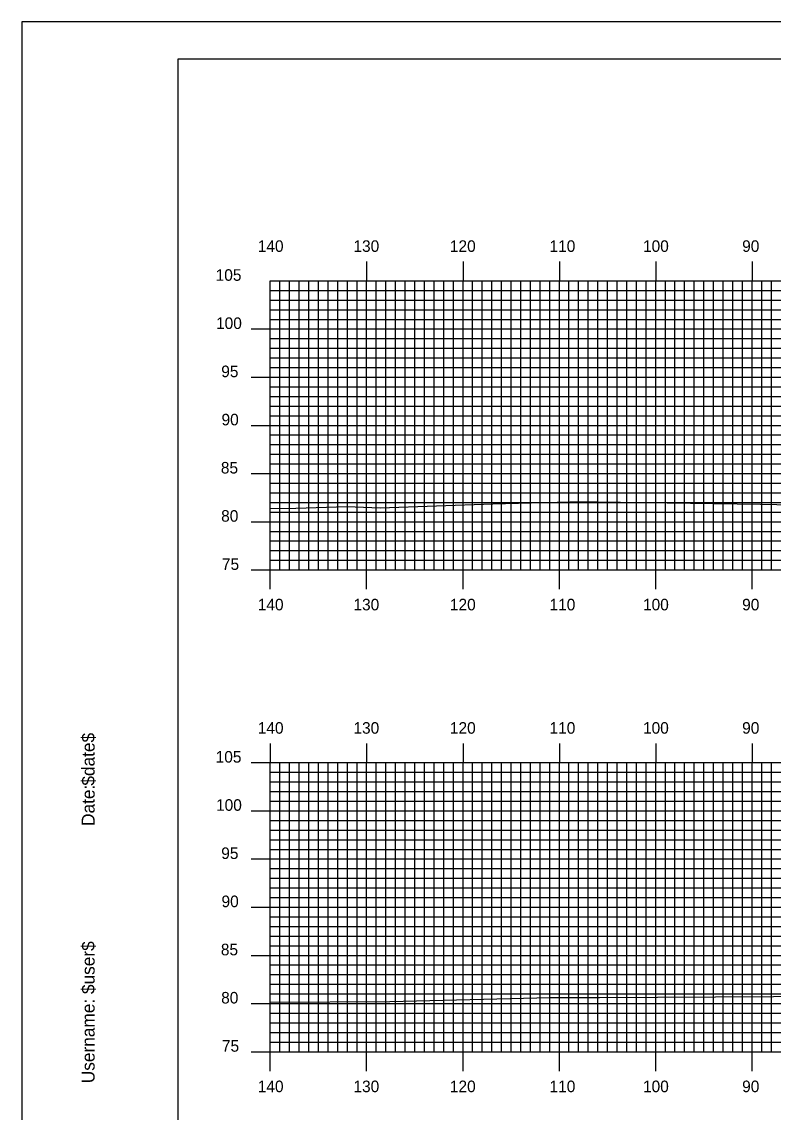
# Model space of a CAD drawing. Extents: x 1757462 to 1757806, y 442591 to 442811.
# Drawn here: x 1757462.3 to 1757540.3, y 442697.4 to 442810.5 of the extents above; entities that cross this region are included whole.
import ezdxf

# ---------------------------------------------------------------- set-up
doc = ezdxf.new("R2010")
doc.units = 0
for name, color, linetype in [('BORDER', 7, 'Continuous'), ('H_V ANNOTATION', 7, 'Continuous'), ('MAJOR', 7, 'Continuous'), ('MINOR', 7, 'Continuous'), ('PLOT BOUNDARY', 7, 'Continuous'), ('S_Roadway_Centerline', 7, 'Continuous')]:
    doc.layers.add(name, color=color, linetype=linetype)

msp = doc.modelspace()

# ---------------------------------------------------------------- linework, layer by layer
at = {"layer": 'BORDER'}
msp.add_lwpolyline([(1757478.51, 442596.67), (1757798.51, 442596.67), (1757798.51, 442806.67), (1757478.51, 442806.67)], close=True, dxfattribs=at)
at = {"layer": 'MAJOR'}
for p, q in [((1757498.11, 442785.67), (1757498.11, 442783.67)), ((1757508.11, 442785.67), (1757508.11, 442783.67)), ((1757518.11, 442785.67), (1757518.11, 442783.67)), ((1757528.11, 442785.67), (1757528.11, 442783.67)), ((1757538.11, 442785.67), (1757538.11, 442783.67)), ((1757488.11, 442783.67), (1757768.11, 442783.67)), ((1757488.11, 442753.67), (1757488.11, 442783.67)), ((1757488.11, 442753.67), (1757488.11, 442783.67)), ((1757488.11, 442783.67), (1757768.11, 442783.67)), ((1757498.11, 442753.67), (1757498.11, 442783.67)), ((1757508.11, 442753.67), (1757508.11, 442783.67)), ((1757518.11, 442753.67), (1757518.11, 442783.67)), ((1757528.11, 442753.67), (1757528.11, 442783.67)), ((1757538.11, 442753.67), (1757538.11, 442783.67)), ((1757486.11, 442778.67), (1757488.11, 442778.67)), ((1757488.11, 442778.67), (1757768.11, 442778.67)), ((1757486.11, 442773.67), (1757488.11, 442773.67)), ((1757488.11, 442773.67), (1757768.11, 442773.67)), ((1757486.11, 442768.67), (1757488.11, 442768.67)), ((1757488.11, 442768.67), (1757768.11, 442768.67)), ((1757486.11, 442763.67), (1757488.11, 442763.67)), ((1757488.11, 442763.67), (1757768.11, 442763.67)), ((1757486.11, 442758.67), (1757488.11, 442758.67)), ((1757488.11, 442758.67), (1757768.11, 442758.67)), ((1757486.11, 442753.67), (1757488.11, 442753.67)), ((1757488.11, 442753.67), (1757768.11, 442753.67)), ((1757488.11, 442753.67), (1757768.11, 442753.67)), ((1757488.11, 442751.66), (1757488.11, 442753.67)), ((1757498.11, 442751.66), (1757498.11, 442753.67)), ((1757508.11, 442751.66), (1757508.11, 442753.67)), ((1757518.11, 442751.66), (1757518.11, 442753.67)), ((1757528.11, 442751.66), (1757528.11, 442753.67)), ((1757538.11, 442751.66), (1757538.11, 442753.67)), ((1757488.11, 442735.67), (1757488.11, 442733.67)), ((1757498.11, 442735.67), (1757498.11, 442733.67)), ((1757508.11, 442735.67), (1757508.11, 442733.67)), ((1757518.11, 442735.67), (1757518.11, 442733.67)), ((1757528.11, 442735.67), (1757528.11, 442733.67)), ((1757538.11, 442735.67), (1757538.11, 442733.67)), ((1757486.11, 442733.67), (1757488.11, 442733.67)), ((1757488.11, 442733.67), (1757768.11, 442733.67)), ((1757488.11, 442703.67), (1757488.11, 442733.67)), ((1757488.11, 442703.67), (1757488.11, 442733.67)), ((1757488.11, 442733.67), (1757768.11, 442733.67)), ((1757498.11, 442703.67), (1757498.11, 442733.67)), ((1757508.11, 442703.67), (1757508.11, 442733.67)), ((1757518.11, 442703.67), (1757518.11, 442733.67)), ((1757528.11, 442703.67), (1757528.11, 442733.67)), ((1757538.11, 442703.67), (1757538.11, 442733.67)), ((1757486.11, 442728.67), (1757488.11, 442728.67)), ((1757488.11, 442728.67), (1757768.11, 442728.67)), ((1757486.11, 442723.67), (1757488.11, 442723.67)), ((1757488.11, 442723.67), (1757768.11, 442723.67)), ((1757486.11, 442718.67), (1757488.11, 442718.67)), ((1757488.11, 442718.67), (1757768.11, 442718.67)), ((1757486.11, 442713.67), (1757488.11, 442713.67)), ((1757488.11, 442713.67), (1757768.11, 442713.67)), ((1757486.11, 442708.67), (1757488.11, 442708.67)), ((1757488.11, 442708.67), (1757768.11, 442708.67)), ((1757486.11, 442703.67), (1757488.11, 442703.67)), ((1757488.11, 442703.67), (1757768.11, 442703.67)), ((1757488.11, 442703.67), (1757768.11, 442703.67)), ((1757488.11, 442701.66), (1757488.11, 442703.67)), ((1757498.11, 442701.66), (1757498.11, 442703.67)), ((1757508.11, 442701.66), (1757508.11, 442703.67)), ((1757518.11, 442701.66), (1757518.11, 442703.67)), ((1757528.11, 442701.66), (1757528.11, 442703.67)), ((1757538.11, 442701.66), (1757538.11, 442703.67))]:
    msp.add_line(p, q, dxfattribs=at)
at = {"layer": 'MINOR'}
for p, q in [((1757489.11, 442753.67), (1757489.11, 442783.67)), ((1757490.11, 442753.67), (1757490.11, 442783.67)), ((1757491.11, 442753.67), (1757491.11, 442783.67)), ((1757492.11, 442753.67), (1757492.11, 442783.67)), ((1757493.11, 442753.67), (1757493.11, 442783.67)), ((1757494.11, 442753.67), (1757494.11, 442783.67)), ((1757495.11, 442753.67), (1757495.11, 442783.67)), ((1757496.11, 442753.67), (1757496.11, 442783.67)), ((1757497.11, 442753.67), (1757497.11, 442783.67)), ((1757499.11, 442753.67), (1757499.11, 442783.67)), ((1757500.11, 442753.67), (1757500.11, 442783.67)), ((1757501.11, 442753.67), (1757501.11, 442783.67)), ((1757502.11, 442753.67), (1757502.11, 442783.67)), ((1757503.11, 442753.67), (1757503.11, 442783.67)), ((1757504.11, 442753.67), (1757504.11, 442783.67)), ((1757505.11, 442753.67), (1757505.11, 442783.67)), ((1757506.11, 442753.67), (1757506.11, 442783.67)), ((1757507.11, 442753.67), (1757507.11, 442783.67)), ((1757509.11, 442753.67), (1757509.11, 442783.67)), ((1757510.11, 442753.67), (1757510.11, 442783.67)), ((1757511.11, 442753.67), (1757511.11, 442783.67)), ((1757512.11, 442753.67), (1757512.11, 442783.67)), ((1757513.11, 442753.67), (1757513.11, 442783.67)), ((1757514.11, 442753.67), (1757514.11, 442783.67)), ((1757515.11, 442753.67), (1757515.11, 442783.67)), ((1757516.11, 442753.67), (1757516.11, 442783.67)), ((1757517.11, 442753.67), (1757517.11, 442783.67)), ((1757519.11, 442753.67), (1757519.11, 442783.67)), ((1757520.11, 442753.67), (1757520.11, 442783.67)), ((1757521.11, 442753.67), (1757521.11, 442783.67)), ((1757522.11, 442753.67), (1757522.11, 442783.67)), ((1757523.11, 442753.67), (1757523.11, 442783.67)), ((1757524.11, 442753.67), (1757524.11, 442783.67)), ((1757525.11, 442753.67), (1757525.11, 442783.67)), ((1757526.11, 442753.67), (1757526.11, 442783.67)), ((1757527.11, 442753.67), (1757527.11, 442783.67)), ((1757529.11, 442753.67), (1757529.11, 442783.67)), ((1757530.11, 442753.67), (1757530.11, 442783.67)), ((1757531.11, 442753.67), (1757531.11, 442783.67)), ((1757532.11, 442753.67), (1757532.11, 442783.67)), ((1757533.11, 442753.67), (1757533.11, 442783.67)), ((1757534.11, 442753.67), (1757534.11, 442783.67)), ((1757535.11, 442753.67), (1757535.11, 442783.67)), ((1757536.11, 442753.67), (1757536.11, 442783.67)), ((1757537.11, 442753.67), (1757537.11, 442783.67)), ((1757539.11, 442753.67), (1757539.11, 442783.67)), ((1757540.11, 442753.67), (1757540.11, 442783.67)), ((1757488.11, 442782.67), (1757768.11, 442782.67)), ((1757488.11, 442782.67), (1757490.11, 442782.67)), ((1757488.11, 442781.67), (1757768.11, 442781.67)), ((1757488.11, 442781.67), (1757490.11, 442781.67)), ((1757488.11, 442780.67), (1757768.11, 442780.67)), ((1757488.11, 442780.67), (1757490.11, 442780.67)), ((1757488.11, 442779.67), (1757768.11, 442779.67)), ((1757488.11, 442779.67), (1757490.11, 442779.67)), ((1757488.11, 442777.67), (1757768.11, 442777.67)), ((1757488.11, 442777.67), (1757490.11, 442777.67)), ((1757488.11, 442776.67), (1757768.11, 442776.67)), ((1757488.11, 442776.67), (1757490.11, 442776.67)), ((1757488.11, 442775.67), (1757768.11, 442775.67)), ((1757488.11, 442775.67), (1757490.11, 442775.67)), ((1757488.11, 442774.67), (1757768.11, 442774.67)), ((1757488.11, 442774.67), (1757490.11, 442774.67)), ((1757488.11, 442772.67), (1757768.11, 442772.67)), ((1757488.11, 442772.67), (1757490.11, 442772.67)), ((1757488.11, 442771.67), (1757768.11, 442771.67)), ((1757488.11, 442771.67), (1757490.11, 442771.67)), ((1757488.11, 442770.67), (1757768.11, 442770.67)), ((1757488.11, 442770.67), (1757490.11, 442770.67)), ((1757488.11, 442769.67), (1757768.11, 442769.67)), ((1757488.11, 442769.67), (1757490.11, 442769.67)), ((1757488.11, 442767.67), (1757768.11, 442767.67)), ((1757488.11, 442767.67), (1757490.11, 442767.67)), ((1757488.11, 442766.67), (1757768.11, 442766.67)), ((1757488.11, 442766.67), (1757490.11, 442766.67)), ((1757488.11, 442765.67), (1757768.11, 442765.67)), ((1757488.11, 442765.67), (1757490.11, 442765.67)), ((1757488.11, 442764.67), (1757768.11, 442764.67)), ((1757488.11, 442764.67), (1757490.11, 442764.67)), ((1757488.11, 442762.67), (1757768.11, 442762.67)), ((1757488.11, 442762.67), (1757490.11, 442762.67)), ((1757488.11, 442761.67), (1757768.11, 442761.67)), ((1757488.11, 442761.67), (1757490.11, 442761.67)), ((1757488.11, 442760.67), (1757768.11, 442760.67)), ((1757488.11, 442760.67), (1757490.11, 442760.67)), ((1757488.11, 442759.67), (1757768.11, 442759.67)), ((1757488.11, 442759.67), (1757490.11, 442759.67)), ((1757488.11, 442757.67), (1757768.11, 442757.67)), ((1757488.11, 442757.67), (1757490.11, 442757.67)), ((1757488.11, 442756.67), (1757768.11, 442756.67)), ((1757488.11, 442756.67), (1757490.11, 442756.67)), ((1757488.11, 442755.67), (1757768.11, 442755.67)), ((1757488.11, 442755.67), (1757490.11, 442755.67)), ((1757488.11, 442754.67), (1757768.11, 442754.67)), ((1757488.11, 442754.67), (1757490.11, 442754.67)), ((1757489.11, 442703.67), (1757489.11, 442733.67)), ((1757490.11, 442703.67), (1757490.11, 442733.67)), ((1757491.11, 442703.67), (1757491.11, 442733.67)), ((1757492.11, 442703.67), (1757492.11, 442733.67)), ((1757493.11, 442703.67), (1757493.11, 442733.67)), ((1757494.11, 442703.67), (1757494.11, 442733.67)), ((1757495.11, 442703.67), (1757495.11, 442733.67)), ((1757496.11, 442703.67), (1757496.11, 442733.67)), ((1757497.11, 442703.67), (1757497.11, 442733.67)), ((1757499.11, 442703.67), (1757499.11, 442733.67)), ((1757500.11, 442703.67), (1757500.11, 442733.67)), ((1757501.11, 442703.67), (1757501.11, 442733.67)), ((1757502.11, 442703.67), (1757502.11, 442733.67)), ((1757503.11, 442703.67), (1757503.11, 442733.67)), ((1757504.11, 442703.67), (1757504.11, 442733.67)), ((1757505.11, 442703.67), (1757505.11, 442733.67)), ((1757506.11, 442703.67), (1757506.11, 442733.67)), ((1757507.11, 442703.67), (1757507.11, 442733.67)), ((1757509.11, 442703.67), (1757509.11, 442733.67)), ((1757510.11, 442703.67), (1757510.11, 442733.67)), ((1757511.11, 442703.67), (1757511.11, 442733.67)), ((1757512.11, 442703.67), (1757512.11, 442733.67)), ((1757513.11, 442703.67), (1757513.11, 442733.67)), ((1757514.11, 442703.67), (1757514.11, 442733.67)), ((1757515.11, 442703.67), (1757515.11, 442733.67)), ((1757516.11, 442703.67), (1757516.11, 442733.67)), ((1757517.11, 442703.67), (1757517.11, 442733.67)), ((1757519.11, 442703.67), (1757519.11, 442733.67)), ((1757520.11, 442703.67), (1757520.11, 442733.67)), ((1757521.11, 442703.67), (1757521.11, 442733.67)), ((1757522.11, 442703.67), (1757522.11, 442733.67)), ((1757523.11, 442703.67), (1757523.11, 442733.67)), ((1757524.11, 442703.67), (1757524.11, 442733.67)), ((1757525.11, 442703.67), (1757525.11, 442733.67)), ((1757526.11, 442703.67), (1757526.11, 442733.67)), ((1757527.11, 442703.67), (1757527.11, 442733.67)), ((1757529.11, 442703.67), (1757529.11, 442733.67)), ((1757530.11, 442703.67), (1757530.11, 442733.67)), ((1757531.11, 442703.67), (1757531.11, 442733.67)), ((1757532.11, 442703.67), (1757532.11, 442733.67)), ((1757533.11, 442703.67), (1757533.11, 442733.67)), ((1757534.11, 442703.67), (1757534.11, 442733.67)), ((1757535.11, 442703.67), (1757535.11, 442733.67)), ((1757536.11, 442703.67), (1757536.11, 442733.67)), ((1757537.11, 442703.67), (1757537.11, 442733.67)), ((1757539.11, 442703.67), (1757539.11, 442733.67)), ((1757540.11, 442703.67), (1757540.11, 442733.67)), ((1757488.11, 442732.67), (1757768.11, 442732.67)), ((1757488.11, 442732.67), (1757490.11, 442732.67)), ((1757488.11, 442731.67), (1757768.11, 442731.67)), ((1757488.11, 442731.67), (1757490.11, 442731.67)), ((1757488.11, 442730.67), (1757768.11, 442730.67)), ((1757488.11, 442730.67), (1757490.11, 442730.67)), ((1757488.11, 442729.67), (1757768.11, 442729.67)), ((1757488.11, 442729.67), (1757490.11, 442729.67)), ((1757488.11, 442727.67), (1757768.11, 442727.67)), ((1757488.11, 442727.67), (1757490.11, 442727.67)), ((1757488.11, 442726.67), (1757768.11, 442726.67)), ((1757488.11, 442726.67), (1757490.11, 442726.67)), ((1757488.11, 442725.67), (1757768.11, 442725.67)), ((1757488.11, 442725.67), (1757490.11, 442725.67)), ((1757488.11, 442724.67), (1757768.11, 442724.67)), ((1757488.11, 442724.67), (1757490.11, 442724.67)), ((1757488.11, 442722.67), (1757768.11, 442722.67)), ((1757488.11, 442722.67), (1757490.11, 442722.67)), ((1757488.11, 442721.67), (1757768.11, 442721.67)), ((1757488.11, 442721.67), (1757490.11, 442721.67)), ((1757488.11, 442720.67), (1757768.11, 442720.67)), ((1757488.11, 442720.67), (1757490.11, 442720.67)), ((1757488.11, 442719.67), (1757768.11, 442719.67)), ((1757488.11, 442719.67), (1757490.11, 442719.67)), ((1757488.11, 442717.67), (1757768.11, 442717.67)), ((1757488.11, 442717.67), (1757490.11, 442717.67)), ((1757488.11, 442716.67), (1757768.11, 442716.67)), ((1757488.11, 442716.67), (1757490.11, 442716.67)), ((1757488.11, 442715.67), (1757768.11, 442715.67)), ((1757488.11, 442715.67), (1757490.11, 442715.67)), ((1757488.11, 442714.67), (1757768.11, 442714.67)), ((1757488.11, 442714.67), (1757490.11, 442714.67)), ((1757488.11, 442712.67), (1757768.11, 442712.67)), ((1757488.11, 442712.67), (1757490.11, 442712.67)), ((1757488.11, 442711.67), (1757768.11, 442711.67)), ((1757488.11, 442711.67), (1757490.11, 442711.67)), ((1757488.11, 442710.67), (1757768.11, 442710.67)), ((1757488.11, 442710.67), (1757490.11, 442710.67)), ((1757488.11, 442709.67), (1757768.11, 442709.67)), ((1757488.11, 442709.67), (1757490.11, 442709.67)), ((1757488.11, 442707.67), (1757768.11, 442707.67)), ((1757488.11, 442707.67), (1757490.11, 442707.67)), ((1757488.11, 442706.67), (1757768.11, 442706.67)), ((1757488.11, 442706.67), (1757490.11, 442706.67)), ((1757488.11, 442705.67), (1757768.11, 442705.67)), ((1757488.11, 442705.67), (1757490.11, 442705.67)), ((1757488.11, 442704.67), (1757768.11, 442704.67)), ((1757488.11, 442704.67), (1757490.11, 442704.67))]:
    msp.add_line(p, q, dxfattribs=at)
at = {"layer": 'PLOT BOUNDARY'}
msp.add_lwpolyline([(1757462.32, 442590.55), (1757802.32, 442590.55), (1757802.32, 442810.55), (1757462.32, 442810.55)], close=True, dxfattribs=at)
at = {"layer": 'S_Roadway_Centerline'}
for points in [[(1757488.11, 442760.05), (1757490.75, 442760.08), (1757496.04, 442760.26), (1757499.5, 442760.11), (1757511.2, 442760.52), (1757519.19, 442760.72), (1757522.04, 442760.72), (1757538.99, 442760.48), (1757544.08, 442760.38)], [(1757488.11, 442708.81), (1757500.51, 442708.88), (1757517.14, 442709.3), (1757522.28, 442709.3), (1757540.34, 442709.4), (1757546.84, 442709.43), (1757549.21, 442709.49), (1757558.21, 442709.71), (1757567.81, 442709.94), (1757582.95, 442709.99), (1757602.84, 442710.29), (1757603.69, 442710.3), (1757604.27, 442710.33), (1757622.81, 442710.66), (1757627.39, 442710.58), (1757634.8, 442710.66), (1757641.39, 442710.72), (1757651.4, 442710.78), (1757660.08, 442710.84), (1757662.16, 442710.84), (1757666.74, 442710.86), (1757678.09, 442711.1), (1757681.09, 442710.97), (1757696.82, 442711.01)]]:
    msp.add_lwpolyline(points, dxfattribs=at)

# ---------------------------------------------------------------- texts
at = {"layer": 'BORDER'}
for s, p in [('$date$', (1757469.88, 442731.28)), ('$date$', (1757469.88, 442731.28)), ('Date:', (1757469.88, 442727.1)), ('Date:', (1757469.88, 442727.1)), ('$user$', (1757469.88, 442709.65)), ('$user$', (1757469.88, 442709.65)), ('Username:', (1757469.88, 442700.4)), ('Username:', (1757469.88, 442700.4))]:
    msp.add_text(s, height=1.339, rotation=90, dxfattribs=at).set_placement(p)
at = {"layer": 'H_V ANNOTATION'}
for s, p in [('140', (1757486.81, 442786.67)), ('130', (1757496.74, 442786.67)), ('120', (1757506.75, 442786.67)), ('110', (1757517.09, 442786.67)), ('100', (1757526.79, 442786.67)), ('90', (1757537.08, 442786.67)), ('105', (1757482.44, 442783.67)), ('100', (1757482.48, 442778.67)), ('95', (1757483.02, 442773.67)), ('90', (1757483.05, 442768.67)), ('85', (1757482.98, 442763.67)), ('80', (1757483.01, 442758.67)), ('75', (1757483.09, 442753.67)), ('140', (1757486.81, 442749.47)), ('130', (1757496.74, 442749.47)), ('120', (1757506.75, 442749.47)), ('110', (1757517.09, 442749.47)), ('100', (1757526.79, 442749.47)), ('90', (1757537.08, 442749.47)), ('140', (1757486.81, 442736.67)), ('130', (1757496.74, 442736.67)), ('120', (1757506.75, 442736.67)), ('110', (1757517.09, 442736.67)), ('100', (1757526.79, 442736.67)), ('90', (1757537.08, 442736.67)), ('105', (1757482.44, 442733.67)), ('100', (1757482.48, 442728.67)), ('95', (1757483.02, 442723.67)), ('90', (1757483.05, 442718.67)), ('85', (1757482.98, 442713.67)), ('80', (1757483.01, 442708.67)), ('75', (1757483.09, 442703.67)), ('140', (1757486.81, 442699.47)), ('130', (1757496.74, 442699.47)), ('120', (1757506.75, 442699.47)), ('110', (1757517.09, 442699.47)), ('100', (1757526.79, 442699.47)), ('90', (1757537.08, 442699.47))]:
    msp.add_text(s, height=1.2, dxfattribs=at).set_placement(p)
at = {"layer": 'MAJOR'}
for p in [(1757488.1, 442753.67), (1757488.1, 442703.67)]:
    msp.add_text('-', height=0.012, dxfattribs=at).set_placement(p)

doc.saveas('drawing.dxf')
